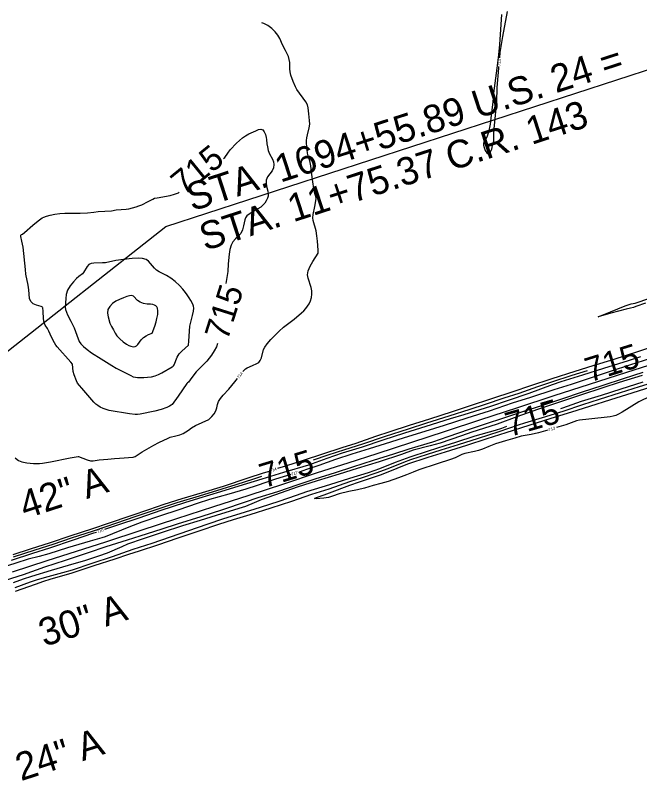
# Model space of a CAD drawing. Extents: x -468548933 to 3387700, y -306089263 to 1207014.
# Drawn here: x 1835390 to 1836234, y 535137 to 536172 of the extents above; entities that cross this region are included whole.
import ezdxf

# ---------------------------------------------------------------- set-up
doc = ezdxf.new("R2010")
doc.units = 0
for name, color, linetype in [('DT_X_Contour_Minor', 7, 'Continuous'), ('Level 14', 7, 'Continuous'), ('Level 19', 7, 'Continuous'), ('Level 40', 7, 'Continuous')]:
    doc.layers.add(name, color=color, linetype=linetype)

msp = doc.modelspace()

# ---------------------------------------------------------------- linework, layer by layer
at = {"layer": 'DT_X_Contour_Minor'}
for points in [[(1836044.9, 536114.6), (1836045.6, 536121.7), (1836046, 536124.1), (1836049.3, 536143.2), (1836055.3, 536177.1)], [(1836047.2, 536173), (1836047, 536166.3), (1836044.6, 536132.6), (1836043.4, 536118.6), (1836040.9, 536100.2), (1836036.4, 536066.6), (1836035.4, 536054.6), (1836033.5, 536036.8), (1836031.9, 536024.5), (1836029.8, 536013.8), (1836027.5, 536007), (1836025.2, 536003.3), (1836023.5, 536001), (1836022.8, 535998.8), (1836022.9, 535996.2), (1836023.9, 535993.1), (1836025.4, 535989.3), (1836027.4, 535986.1), (1836029.4, 535984.4), (1836031.4, 535985.4), (1836033, 535988), (1836034.2, 535991.1), (1836034.9, 535995.8), (1836035.2, 535997.4), (1836036.7, 536001.6), (1836036.9, 536013.8), (1836039.2, 536036.9), (1836040.8, 536054.7), (1836041.6, 536074.3), (1836043.6, 536100.3), (1836043.8, 536102.6)], [(1835697.7, 535690.5), (1835698.4, 535691.4), (1835701.1, 535693.9), (1835703.2, 535695.2), (1835710.8, 535698.5), (1835716.5, 535701), (1835719, 535702.6), (1835721.1, 535705.1), (1835722.7, 535708.7), (1835725.7, 535720.2), (1835727.4, 535723.5), (1835730.5, 535727.8), (1835735.6, 535733.6), (1835746.5, 535744.9), (1835752.4, 535750.2), (1835766.8, 535761.3), (1835776.8, 535769.6), (1835780, 535772.6), (1835782.6, 535775.4), (1835785, 535778.5), (1835787.3, 535781.9), (1835789.1, 535785.8), (1835790.3, 535790.2), (1835790.9, 535794.9), (1835790.7, 535799.5), (1835789.9, 535803.8), (1835785.7, 535816.4), (1835785.2, 535821.1), (1835786.1, 535826.6), (1835788.7, 535832.9), (1835792.2, 535839.2), (1835799.3, 535850.3), (1835799.3, 535854.6), (1835798.7, 535866.7), (1835797.8, 535873.9), (1835796.5, 535880.5), (1835792.7, 535894.6), (1835792.4, 535898.2), (1835792.8, 535902.4), (1835794.9, 535913.6), (1835796.8, 535923.9), (1835796.7, 535925.3), (1835794.5, 535932.8), (1835792.6, 535943.4), (1835790.6, 535959.8), (1835789.5, 535968.2), (1835788, 535975), (1835785.9, 535981.7), (1835785, 535985.5), (1835784.4, 535989.9), (1835783.8, 535998.9), (1835783.8, 536002.7), (1835784.1, 536006.2), (1835784.8, 536010.1), (1835787.2, 536019.6), (1835788, 536024.7), (1835787.8, 536029.7), (1835786.6, 536038.7), (1835786.1, 536046.6), (1835785, 536050.7), (1835782.6, 536055.1), (1835770.7, 536071.6), (1835768.7, 536075.1), (1835765.4, 536082.5), (1835762.6, 536090.9), (1835761.5, 536095.3), (1835760.9, 536099.7), (1835760.9, 536108.1), (1835760.4, 536112.2), (1835759.1, 536116.4), (1835755.1, 536124.5), (1835751.4, 536132), (1835747.6, 536140.3), (1835745, 536145), (1835741.4, 536149.7), (1835736.7, 536154.1), (1835731.4, 536157.9), (1835726.1, 536160.7), (1835723.1, 536161.7)], [(1835671.4, 535978.3), (1835673.1, 535979.8), (1835677.1, 535985.7), (1835680.6, 535989.9), (1835689.1, 535999), (1835693.1, 536002.8), (1835696.9, 536006.2), (1835701.1, 536009.1), (1835705.7, 536011.7), (1835715.1, 536015.9), (1835718.9, 536017.4), (1835721.9, 536018), (1835724.5, 536017.1), (1835726.6, 536014.4), (1835728.2, 536010.6), (1835729.3, 536006.9), (1835729.6, 536004), (1835730, 535998.1), (1835730.7, 535993.9), (1835732, 535989.1), (1835733.8, 535984.6), (1835737.8, 535977.5), (1835739.2, 535974), (1835739.6, 535970.1), (1835738.9, 535965.8), (1835737, 535961.5), (1835731, 535953.4), (1835729, 535949), (1835728.9, 535944), (1835730.1, 535938.9), (1835731.4, 535934.3), (1835732, 535930.6), (1835731.8, 535927.5), (1835730.9, 535924.5), (1835729.3, 535921.2), (1835727.2, 535918), (1835724.6, 535915.1), (1835721.8, 535912.7), (1835714.8, 535908.4), (1835706.3, 535903.2), (1835703, 535900.6), (1835701.1, 535898.2), (1835700.1, 535895.6), (1835698.6, 535887.3), (1835697.1, 535882), (1835694.7, 535877), (1835691.4, 535873), (1835687.6, 535869.5), (1835684.2, 535865.8), (1835681.8, 535861.1), (1835680.1, 535855.5), (1835679, 535849.2), (1835677.9, 535836), (1835677.2, 535825.5), (1835674.7, 535809.2)], [(1835663.5, 535728.4), (1835662, 535723.7), (1835659, 535718.2), (1835655.2, 535712.6), (1835648.7, 535704.3), (1835643.9, 535699.3), (1835637.9, 535693.5), (1835634.5, 535689.9), (1835628.6, 535682.1), (1835624, 535675.8), (1835622.8, 535675), (1835622, 535674.1), (1835610.1, 535657.1), (1835601.9, 535645.9), (1835600.5, 535644.8), (1835598.3, 535643.4), (1835595, 535641.9), (1835586.9, 535638.9), (1835578.6, 535636.8), (1835558.6, 535632.5), (1835554.9, 535632.1), (1835551.9, 535632.2), (1835544.5, 535633.2), (1835517, 535637.6), (1835512.9, 535638.8), (1835508.7, 535640.4), (1835504.7, 535642.2), (1835501.3, 535644.2), (1835498.6, 535646.3), (1835495.9, 535649), (1835482.5, 535664.7), (1835474, 535674.6), (1835472.7, 535677.6), (1835469.5, 535685.8), (1835468.3, 535690.3), (1835467.1, 535700.1), (1835465.2, 535703.1), (1835446.6, 535723.9), (1835444.8, 535726.2), (1835442.9, 535729.1), (1835439, 535736.6), (1835435.3, 535744.9), (1835433.6, 535748.3), (1835430.3, 535753.1), (1835429.1, 535756.4), (1835428.2, 535761.4), (1835427.4, 535771.8), (1835427.1, 535776.3), (1835426.8, 535777.1), (1835426.3, 535777.7), (1835425, 535778.3), (1835418.6, 535780.2), (1835414.2, 535782), (1835410.8, 535784.8), (1835409.2, 535789.1), (1835408.2, 535800.7), (1835407.1, 535807.3), (1835404, 535822), (1835403.7, 535828.4), (1835400.4, 535858.5), (1835398.6, 535866.6), (1835397.3, 535873), (1835397.5, 535874.6), (1835398.2, 535875.4), (1835399.5, 535875.9), (1835402.2, 535878.3), (1835413.4, 535888.1), (1835420.9, 535894.2), (1835426.2, 535898), (1835428.6, 535899.2), (1835432, 535900.4), (1835437, 535901.7), (1835443.2, 535903), (1835450, 535903.9), (1835456.8, 535904.4), (1835471.4, 535904.3), (1835477.6, 535904.4), (1835487.6, 535904.9), (1835495.9, 535905.8), (1835502.1, 535906.7), (1835519.8, 535907.7), (1835526.5, 535908.7), (1835539.7, 535909.7), (1835543.5, 535910.4), (1835553.5, 535913.1), (1835557.1, 535914.2), (1835561, 535915.7), (1835569.6, 535920.1), (1835575.7, 535923.5), (1835578.1, 535924.5), (1835581.5, 535925.2), (1835599.2, 535928.5), (1835605.3, 535930), (1835610.6, 535932.1), (1835611.6, 535932.8)], [(1835625, 535790.1), (1835622.5, 535793.9), (1835620.1, 535797.2), (1835616.6, 535801.5), (1835611.9, 535806.6), (1835606.2, 535811.9), (1835600.3, 535816.6), (1835594.5, 535820.2), (1835584.6, 535825.1), (1835580.9, 535827.5), (1835577.9, 535830.1), (1835575.3, 535833), (1835572.9, 535836.2), (1835570.2, 535839.4), (1835566.7, 535841.8), (1835562, 535843.1), (1835556.7, 535843.5), (1835548.1, 535843.2), (1835536.3, 535842), (1835525.7, 535840.4), (1835511.9, 535837.4), (1835507.9, 535837.1), (1835496, 535837), (1835492.4, 535836.5), (1835489.4, 535835), (1835487.1, 535832.4), (1835482.3, 535824.1), (1835480.7, 535822.5), (1835475.7, 535818.7), (1835472.8, 535816), (1835468.7, 535811.7), (1835464.3, 535806.2), (1835460.7, 535800.3), (1835458.7, 535794.5), (1835458, 535789.2), (1835457.5, 535777.5), (1835457.9, 535774.3), (1835458.9, 535770.8), (1835460.5, 535766.9), (1835464.9, 535758.5), (1835467.4, 535754.1), (1835469.7, 535749.4), (1835473.3, 535739.4), (1835476.4, 535731.1), (1835478.5, 535727.6), (1835481.9, 535724), (1835486.9, 535719.9), (1835493, 535715.5), (1835506, 535707.3), (1835520.2, 535698.5), (1835526.2, 535694.7), (1835546.1, 535684.8), (1835549.3, 535683.3), (1835552.2, 535682.5), (1835555.2, 535682.1), (1835563.5, 535682.3), (1835568.8, 535682.7), (1835574.2, 535683.4), (1835579.1, 535684.7), (1835583.7, 535686.4), (1835587.9, 535688.5), (1835602, 535696.5), (1835603, 535697.1), (1835603.7, 535698), (1835604.6, 535699.5), (1835608.9, 535709.7), (1835611.6, 535714.1), (1835615.1, 535717.9), (1835624.2, 535726.1), (1835624.6, 535731.3), (1835625.8, 535751.5), (1835629.5, 535766), (1835630.7, 535771.8), (1835631.1, 535775.9), (1835630.7, 535778.8), (1835629.8, 535781.2), (1835627.1, 535786.4), (1835625, 535790.1)], [(1835575, 535742.3), (1835578.7, 535751.8), (1835580.3, 535757.4), (1835581.4, 535762.2), (1835582.4, 535767.6), (1835582.8, 535772.4), (1835582.3, 535775.8), (1835581.2, 535777.9), (1835579.7, 535779.2), (1835578, 535780.1), (1835575.9, 535780.8), (1835572.7, 535781.3), (1835568.3, 535781.6), (1835563.3, 535782.3), (1835558.7, 535783.9), (1835555.1, 535786.5), (1835549.9, 535792), (1835547.4, 535793.1), (1835544.5, 535792.8), (1835540.8, 535791.7), (1835536.2, 535790.1), (1835531, 535787.9), (1835525.8, 535785.3), (1835521.1, 535782.1), (1835517.5, 535778.4), (1835515.2, 535774), (1835514.7, 535769.2), (1835515.4, 535764.2), (1835517.8, 535755.9), (1835519.9, 535751), (1835522.8, 535746.9), (1835525, 535742.2), (1835527.4, 535738.7), (1835531.2, 535734.6), (1835535.8, 535730.6), (1835540.1, 535727.3), (1835543.6, 535725.4), (1835546.2, 535724.5), (1835549.9, 535723.9), (1835552, 535724.3), (1835553.6, 535725.1), (1835555.5, 535726.9), (1835560.3, 535733.1), (1835563.3, 535736.3), (1835566.8, 535738.7), (1835570.2, 535740.5), (1835575, 535742.3)], [(1836242, 535782.8), (1836229.1, 535778.4), (1836225.9, 535776.9), (1836221.7, 535776.2), (1836215.8, 535774.8), (1836195.3, 535769.1), (1836178, 535764.3), (1836178.9, 535764.7), (1836194.7, 535771.1), (1836214.5, 535779), (1836222.8, 535781.9), (1836228.1, 535782.8), (1836233.3, 535784.4), (1836251.6, 535790.9)], [(1835745, 535559.5), (1835755.9, 535563), (1835779.4, 535570.4), (1835805.7, 535579.2), (1835831.7, 535587.5), (1835851, 535593.7), (1835877.4, 535602.8), (1835896.6, 535609.2), (1835922.7, 535617.7), (1835950.3, 535626.5), (1835981.1, 535636.3), (1836005.3, 535644.4), (1836032.8, 535653.6), (1836064.2, 535663.7), (1836085.6, 535670.9), (1836115.9, 535680.8), (1836147.1, 535690.8), (1836171.3, 535698.3), (1836199.5, 535707.1), (1836231.5, 535717.6), (1836253.2, 535724.6)], [(1836294.5, 535722.5), (1836273.3, 535715.9), (1836248.9, 535708.1), (1836220.2, 535698.9), (1836195.4, 535690.9), (1836165.7, 535681.1), (1836141.7, 535673), (1836118.1, 535665.4), (1836086.5, 535655.3), (1836061.9, 535647.4), (1836030.4, 535636.9), (1836000.6, 535627.1), (1835969.7, 535617.5), (1835943.6, 535609.3), (1835915.9, 535600.7), (1835897.4, 535594.8), (1835868.4, 535585.9), (1835845, 535578.6), (1835822.7, 535571.4), (1835800.3, 535563.4), (1835783.8, 535557.7), (1835773.9, 535554.5)], [(1835511.1, 535477.2), (1835528.7, 535483.2), (1835557.4, 535492.8), (1835587.2, 535502.9), (1835619.1, 535513.2), (1835637.9, 535519.1), (1835667.7, 535528.1), (1835692.6, 535535.8), (1835723.8, 535545.3), (1835753.2, 535554.2), (1835786.6, 535564.3), (1835811.4, 535573.1), (1835832.4, 535580.4), (1835859.2, 535588.7), (1835887.4, 535597.8), (1835916.6, 535607.4), (1835945.4, 535616.5), (1835978.4, 535626.8), (1835997, 535632.4), (1836033, 535643.4), (1836056.7, 535651.5), (1836084.9, 535661.2), (1836116.1, 535672.6), (1836127.9, 535676.7), (1836157.4, 535686.1), (1836185.6, 535695), (1836218.9, 535705.4), (1836235.7, 535710.8)], [(1836238.4, 535689), (1836211.7, 535680.4), (1836184.4, 535671.4), (1836155.2, 535662), (1836129.8, 535653.6), (1836102.7, 535644.6), (1836074.4, 535635.4), (1836052.6, 535628), (1836022.6, 535618.2), (1836003.5, 535611.9), (1835974.7, 535601.9), (1835954.1, 535595), (1835934, 535588.9), (1835922, 535585.2), (1835901.1, 535578.5), (1835873.7, 535570), (1835845.9, 535561.1), (1835822.2, 535553.6), (1835795.1, 535545), (1835771.7, 535537.2), (1835744.2, 535527.9), (1835717.8, 535519.5), (1835700.7, 535513.6), (1835669.9, 535503.2), (1835640.9, 535494.1), (1835608.9, 535484), (1835588, 535477.3), (1835558.1, 535467.6), (1835541, 535462.4), (1835512.1, 535453.6), (1835488.4, 535445.3), (1835457.2, 535434.9), (1835429.6, 535425.8), (1835400.6, 535415.6), (1835376, 535407.7)], [(1835792.9, 535570.8), (1835813.1, 535577.8), (1835835.4, 535585), (1835859.8, 535592.7), (1835890.4, 535603), (1835921.4, 535613.1), (1835946.2, 535620.9), (1835976.7, 535630.6), (1836005, 535639.3), (1836025.8, 535646.2), (1836051, 535654.7), (1836071.2, 535661.3), (1836096.6, 535670.3), (1836115.2, 535676.6), (1836142.8, 535685.4), (1836163.4, 535691.9)], [(1836237.3, 535685.2), (1836206.6, 535675.5), (1836184.5, 535668.4), (1836154, 535658.6), (1836125.7, 535649.1), (1836096, 535639), (1836067.8, 535629.3), (1836041.5, 535619.3), (1836031.5, 535615.9), (1836007, 535608.2), (1835993.3, 535603.6), (1835964.2, 535593.5), (1835950.8, 535589.8), (1835927.8, 535583.9), (1835912, 535578.3), (1835881.9, 535568.1), (1835852.2, 535559.4), (1835827.7, 535551.8), (1835798.1, 535542.6), (1835771.2, 535534.1), (1835749.3, 535526.4), (1835722.2, 535516.8), (1835712.8, 535512.9), (1835701, 535508), (1835692.2, 535505.1), (1835661.7, 535495.6), (1835639.7, 535488.8), (1835616, 535481.8), (1835588.4, 535472.9), (1835563, 535464.3), (1835541.6, 535456.8), (1835533.9, 535453.6), (1835514.2, 535444.9), (1835502.6, 535440.7), (1835484.8, 535435.1), (1835461.4, 535428.2), (1835438.2, 535421.4), (1835411.8, 535413.4), (1835400.4, 535409.6), (1835387.2, 535404.9)], [(1836261.5, 535678.2), (1836233.5, 535669.5), (1836207.9, 535661.5), (1836179.4, 535652.4), (1836156.7, 535645.3), (1836130.2, 535636.4), (1836102.1, 535627.6), (1836078.6, 535620.5), (1836069.9, 535617.8), (1836043.9, 535608.7), (1836015.6, 535600), (1835988.5, 535591.4), (1835965.1, 535583.9), (1835947, 535578.1), (1835924.3, 535570.8), (1835915, 535567.5), (1835893.4, 535558.9), (1835877.6, 535552.9), (1835858.7, 535546.6), (1835841.9, 535541.2), (1835813.9, 535531.3), (1835790.5, 535524), (1835763.5, 535514.8), (1835735.4, 535505.5), (1835707, 535496.7), (1835684.3, 535489.7), (1835664.7, 535483.6), (1835638, 535474.5), (1835609.6, 535465), (1835582.2, 535455.8), (1835557.4, 535447.6), (1835542.9, 535442.8), (1835524.7, 535436.8), (1835496, 535427.5), (1835466.4, 535417.8), (1835436.7, 535409.1), (1835427.9, 535406.6), (1835416.6, 535402.6), (1835389.6, 535392.8)], [(1835389.8, 535573.9), (1835392.2, 535571.6), (1835394.3, 535570.1), (1835396.4, 535569.1), (1835398.7, 535568.3), (1835405.7, 535567.1), (1835414.7, 535566.1), (1835418.6, 535565.9), (1835422.4, 535566.1), (1835426.8, 535566.5), (1835437.6, 535568.4), (1835464, 535573.5), (1835474.7, 535575.4), (1835475.4, 535575.3), (1835487, 535570.8), (1835491.5, 535569.7), (1835495.4, 535569.7), (1835503.5, 535571.1), (1835515.2, 535572), (1835524, 535572.6), (1835530.7, 535573.4), (1835549.4, 535574.8), (1835551.8, 535575.7), (1835561.5, 535581.7), (1835577, 535591), (1835583.8, 535594.6), (1835596.5, 535600.4), (1835599.2, 535601.4), (1835607, 535603.4), (1835612.2, 535604.8), (1835616.9, 535606.5), (1835620.6, 535608.7), (1835623.9, 535611.2), (1835628, 535614.1), (1835633.7, 535617.2), (1835651.5, 535625.5), (1835655.8, 535629.5), (1835658.7, 535633), (1835661.2, 535637), (1835662.5, 535641.2), (1835663.4, 535645.6), (1835664.8, 535649.9), (1835667.4, 535654.1), (1835670.9, 535658.3), (1835678.6, 535666.7), (1835686.6, 535676.2), (1835690.4, 535681)], [(1836110.2, 535611.3), (1836106.7, 535610.3), (1836097.4, 535607.5), (1836087.4, 535605.4), (1836073.7, 535603.1), (1836065.2, 535600.4), (1836052.9, 535596.5), (1836039.1, 535592.5), (1836030.1, 535589.2), (1836021.4, 535585.6), (1836016.2, 535583.6), (1836011, 535582.1), (1835997.6, 535579.6), (1835993.7, 535578.1), (1835984.6, 535573.8), (1835978.3, 535571.3), (1835960.4, 535565.4), (1835935.7, 535557.4), (1835927.7, 535554.3), (1835918.9, 535550.6), (1835908.2, 535546.5), (1835894, 535541.7), (1835884, 535539.2), (1835873.6, 535536.3), (1835862, 535532.8), (1835852.4, 535530.6), (1835840.9, 535528.3), (1835827.8, 535525), (1835819, 535521.8), (1835813.6, 535520.1), (1835807, 535519.2), (1835796.7, 535518.2), (1835794.6, 535518.6), (1835797.1, 535520), (1835807.4, 535523.7), (1835814.8, 535526.2), (1835842.1, 535536.6), (1835855.5, 535541.3), (1835883.9, 535550.9), (1835891.8, 535554), (1835920.6, 535565.5), (1835948.3, 535574.4), (1835971.6, 535581.8), (1836000.6, 535591), (1836028.1, 535599.9), (1836053.4, 535608), (1836084.6, 535618), (1836114.6, 535627.3), (1836142.5, 535635.7), (1836166.6, 535643.4), (1836194.9, 535652.4), (1836224, 535661.7), (1836250.9, 535670.2)], [(1836324.1, 535677.3), (1836297.2, 535669), (1836277.2, 535664.7), (1836261.4, 535660), (1836252.5, 535657.7), (1836248, 535656.3), (1836243.2, 535654.5), (1836238.3, 535652.2), (1836233.1, 535649.3), (1836210.6, 535635.5), (1836205.7, 535632.8), (1836201.9, 535631), (1836198.4, 535630), (1836194.3, 535629.3), (1836165.3, 535625.9), (1836152.9, 535624.4), (1836148.6, 535623.6), (1836134.2, 535618.2), (1836121.7, 535614.6)], [(1836238.3, 535676), (1836208.7, 535666.7), (1836182.1, 535658.1), (1836155.2, 535649.9), (1836129.9, 535640.8), (1836127.2, 535639.9)], [(1836054.2, 535616.2), (1836047.2, 535613.5), (1836038.9, 535610.8), (1836011.3, 535602.8), (1835984.9, 535594.6), (1835970.7, 535589.8), (1835948.2, 535582.5), (1835923.4, 535574.7), (1835903.4, 535567.2), (1835882.2, 535559), (1835867, 535553.5), (1835841.8, 535545.9), (1835814.8, 535537), (1835783.6, 535527.6), (1835769.6, 535522.9), (1835746.1, 535514.7), (1835720.8, 535506.5), (1835693.5, 535497.9), (1835671.6, 535491.1), (1835648.8, 535483.4), (1835624.3, 535475), (1835599.1, 535466.4), (1835574.3, 535457.7), (1835549, 535449.7), (1835520.9, 535440), (1835493.2, 535430.8), (1835466.7, 535422), (1835453.7, 535418.1), (1835428.8, 535411.3), (1835418.1, 535408.4), (1835409.9, 535405.7), (1835389.2, 535398)], [(1835387.1, 535443), (1835410.4, 535450.5), (1835437.6, 535459.4), (1835463.9, 535468.1), (1835494.9, 535478.2), (1835516.1, 535485.3), (1835546.6, 535495.6), (1835570.4, 535503.8), (1835591.4, 535510.9), (1835615.5, 535518.5), (1835642.9, 535526.8), (1835671.6, 535535.5), (1835704.8, 535546.5), (1835725.6, 535553.2), (1835733.6, 535555.8)], [(1835762.4, 535551), (1835741.8, 535544.7), (1835716.8, 535536.1), (1835701.6, 535531.4), (1835678.4, 535524.7), (1835652.7, 535517.2), (1835635.9, 535511.8), (1835610.8, 535503.5), (1835585, 535494.9), (1835560.8, 535486.5), (1835543.3, 535480), (1835511.4, 535467), (1835506.8, 535465.4), (1835491.3, 535460.9), (1835460.6, 535452.2), (1835435.1, 535444.1), (1835422, 535440.5), (1835407.1, 535436.6), (1835390.6, 535431.4), (1835361.8, 535422.2)], [(1835387.5, 535439.7), (1835416.7, 535449.1), (1835441, 535457), (1835466.1, 535465.4), (1835495.5, 535475.2), (1835527, 535485.8), (1835552, 535494.2), (1835582.9, 535504.8), (1835608.6, 535513.2), (1835638.9, 535522.5), (1835669.5, 535531.7), (1835688.4, 535537.8), (1835712.3, 535545.3), (1835723.4, 535548.8)], [(1835384.7, 535435.4), (1835413.6, 535444.6), (1835436.8, 535452.2), (1835468.4, 535462.8), (1835496.1, 535472.1), (1835499.8, 535473.4)]]:
    msp.add_lwpolyline(points, dxfattribs=at)
at = {"layer": 'Level 14'}
msp.add_lwpolyline([(1836265.7, 535705), (1836216.5, 535689.1), (1836165.7, 535672.7), (1836118.2, 535657.3), (1836067.7, 535640.9), (1836018.9, 535624.9), (1835971.3, 535609.4), (1835925.8, 535594.6), (1835878.8, 535579.3), (1835839.6, 535566.6), (1835798.1, 535553.2), (1835752.5, 535538.2), (1835705.5, 535522.8), (1835657.8, 535507.3), (1835607.7, 535491.1), (1835559.8, 535475.5), (1835511.8, 535459.9), (1835462.4, 535444.1), (1835432.7, 535434.3), (1835385.5, 535419.2)], dxfattribs=at)
at = {"layer": 'Level 40'}
for p, q in [((1835593.6, 535886.6), (1836369.2, 536138.4)), ((1835185.7, 535565.7), (1835593.6, 535886.6))]:
    msp.add_line(p, q, dxfattribs=at)

# ---------------------------------------------------------------- texts
at = {"layer": 'Level 19'}
for s, height, rotation, p in [('713', 4, 84.6087, (1836045.9, 536103.2)), ('715', 33, 39.133, (1835617.5, 535927.1)), ('715', 33, 72.5135, (1835676.7, 535730.9)), ('715', 33, 17.2288, (1836166.4, 535675.6)), ('714', 4, 52.122, (1835692.4, 535680.4)), ('715', 33, 16.0314, (1836058.1, 535601.8)), ('713', 4, 16.1001, (1836111.5, 535609.6)), ('715', 33, 16.908, (1835726, 535532.6)), ('714', 4, 17.8534, (1835734.9, 535554.1)), ('717', 4, 17.3721, (1835763.7, 535549.3)), ('716', 4, 18.7644, (1835501, 535471.7))]:
    msp.add_text(s, height=height, rotation=rotation, dxfattribs=at).set_placement(p)
at = {"layer": 'Level 40'}
for s, p in [('STA. 1694+55.89 U.S. 24 =', (1835629, 535906.7)), ('STA. 11+75.37 C.R. 143', (1835646.4, 535853.2)), ('42" A', (1835403.1, 535490.8)), ('30" A', (1835429, 535318.1)), ('24" A', (1835397.6, 535136.5))]:
    msp.add_text(s, height=37.5, rotation=17.9864, dxfattribs=at).set_placement(p)

doc.saveas('drawing.dxf')
